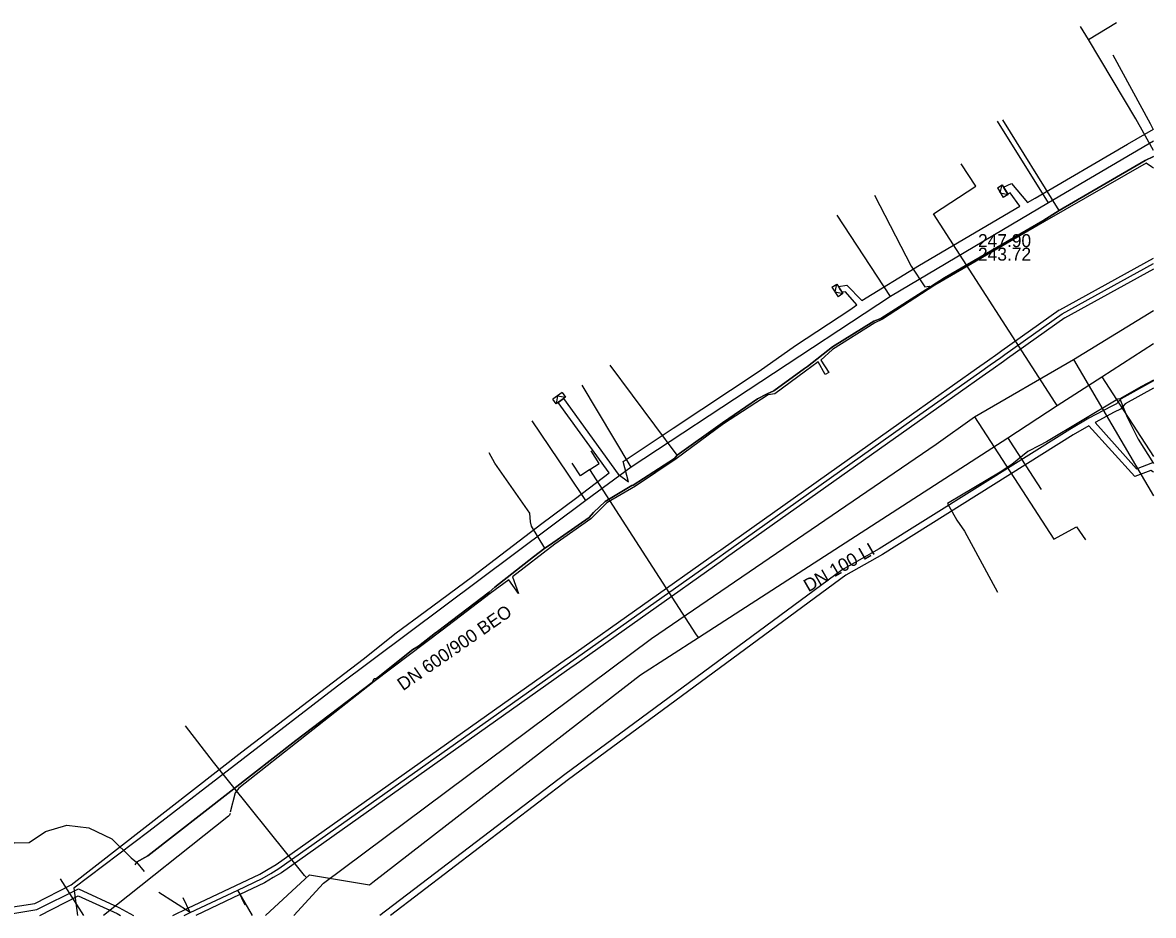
# Model space of a CAD drawing. Extents: x -600391 to -599491, y -1160176 to -1159402.
# Drawn here: x -599560.4 to -599490.8, y -1160176.1 to -1160121.1 of the extents above; entities that cross this region are included whole.
import ezdxf

# ---------------------------------------------------------------- set-up
doc = ezdxf.new("R2010")
doc.units = 0
for name, color, linetype in [('31', 7, 'Continuous'), ('UPC_ok_linie', 7, 'Continuous'), ('Vrstva 1', 7, 'Continuous'), ('Vrstva 10', 7, 'Continuous'), ('Vrstva 12', 7, 'Continuous'), ('Vrstva 13', 7, 'Continuous'), ('Vrstva 15', 7, 'Continuous'), ('Vrstva 16', 7, 'Continuous'), ('Vrstva 42', 7, 'Continuous'), ('Vrstva 43', 7, 'Continuous'), ('Vrstva 55', 7, 'Continuous'), ('Vrstva 9', 7, 'Continuous')]:
    doc.layers.add(name, color=color, linetype=linetype)

# ---------------------------------------------------------------- blocks, each defined once
blk = doc.blocks.new('NN630')
at = {"layer": '31'}
for points in [[(0, -0.7), (-0.7, 0)], [(-0.7, -0.7), (-0.7, 0), (0.7, 0), (0.7, -0.7)], [(-0.7, -0.7), (0.7, -0.7)], [(0, -0.7), (0.7, 0)]]:
    blk.add_lwpolyline(points, dxfattribs=at)

msp = doc.modelspace()

# ---------------------------------------------------------------- linework, layer by layer
at = {"layer": 'UPC_ok_linie'}
for p, q in [((-599496.57, -1160132.67), (-599500.056, -1160127.084)), ((-599520.12, -1160147.73), (-599524.244, -1160142.195)), ((-599553.42, -1160172.81), (-599552.943, -1160173.385))]:
    msp.add_line(p, q, dxfattribs=at)
for points in [[(-599490.773, -1160127.688), (-599490.96, -1160127.33), (-599493.246, -1160123.094)], [(-599490.773, -1160129.332), (-599491.27, -1160129.58), (-599496.57, -1160132.67), (-599497.59, -1160133.29), (-599503.65, -1160136.8), (-599504.44, -1160137.32), (-599504.508, -1160137.366), (-599504.56, -1160137.4), (-599507.57, -1160139.31)], [(-599496.57, -1160132.67), (-599491.27, -1160129.58), (-599490.773, -1160129.332)], [(-599507.946, -1160131.709), (-599505.69, -1160136.09), (-599504.86, -1160137.36), (-599504.58, -1160137.33), (-599504.508, -1160137.366)], [(-599504.508, -1160137.366), (-599504.44, -1160137.32), (-599503.65, -1160136.8), (-599497.59, -1160133.29), (-599496.57, -1160132.67)], [(-599520.12, -1160147.73), (-599517.32, -1160145.74), (-599515.16, -1160144.26), (-599514.56, -1160143.95), (-599514.16, -1160143.76), (-599512.26, -1160142.39), (-599512.08, -1160142.27), (-599510.54, -1160141.05), (-599507.99, -1160139.47), (-599507.57, -1160139.31), (-599504.56, -1160137.4), (-599504.508, -1160137.366)], [(-599507.57, -1160139.31), (-599507.99, -1160139.47), (-599510.54, -1160141.05), (-599512.08, -1160142.27), (-599512.26, -1160142.39), (-599514.16, -1160143.76), (-599514.56, -1160143.95), (-599515.16, -1160144.26), (-599517.32, -1160145.74), (-599520.12, -1160147.73), (-599520.27, -1160147.93), (-599522.82, -1160149.57), (-599522.91, -1160149.6), (-599524.55, -1160150.58), (-599525.27, -1160151.26), (-599525.53, -1160151.57), (-599527.97, -1160153.28), (-599528.26, -1160153.47), (-599528.96, -1160154), (-599531.35, -1160155.86), (-599531.7, -1160156.18), (-599534.87, -1160158.59), (-599535, -1160158.67), (-599536.05, -1160159.49), (-599536.4, -1160159.71), (-599538.64, -1160161.48), (-599538.77, -1160161.51), (-599538.9, -1160161.73), (-599543.61, -1160165.31), (-599547.6, -1160168.42), (-599552.72, -1160172.42), (-599553.42, -1160172.81), (-599553.52, -1160172.96)], [(-599490.773, -1160143.111), (-599491.54, -1160143.52), (-599492.85, -1160144.26)], [(-599492.85, -1160144.26), (-599492.97, -1160144.29), (-599497.35, -1160146.92), (-599497.79, -1160147.13), (-599498.51, -1160147.51), (-599499.5, -1160148.31), (-599500.21, -1160148.77), (-599503.46, -1160150.7), (-599502.89, -1160151.74), (-599502.4, -1160152.42), (-599500.374, -1160156.168)], [(-599492.85, -1160144.26), (-599492.38, -1160145.39), (-599491.72, -1160146.74), (-599490.773, -1160148.25)], [(-599528.26, -1160153.47), (-599529.09, -1160152.11), (-599529.14, -1160151.84), (-599529.19, -1160151.31), (-599531.35, -1160148.22), (-599531.698, -1160147.59)], [(-599528.26, -1160153.47), (-599527.97, -1160153.28), (-599525.53, -1160151.57), (-599525.27, -1160151.26), (-599524.55, -1160150.58), (-599522.91, -1160149.6), (-599522.82, -1160149.57), (-599520.27, -1160147.93), (-599520.12, -1160147.73)], [(-599553.42, -1160172.81), (-599552.72, -1160172.42), (-599547.6, -1160168.42), (-599543.61, -1160165.31), (-599538.9, -1160161.73), (-599538.77, -1160161.51), (-599538.64, -1160161.48), (-599536.4, -1160159.71), (-599536.05, -1160159.49), (-599535, -1160158.67), (-599534.87, -1160158.59), (-599531.7, -1160156.18), (-599531.35, -1160155.86), (-599528.96, -1160154), (-599528.26, -1160153.47)], [(-599561.99, -1160171.02), (-599560.93, -1160171.62), (-599560.04, -1160171.59), (-599559.02, -1160170.91), (-599557.72, -1160170.53), (-599556.35, -1160170.69), (-599554.93, -1160171.36), (-599553.75, -1160172.53), (-599553.42, -1160172.81)]]:
    msp.add_lwpolyline(points, dxfattribs=at)
at = {"layer": 'Vrstva 1'}
msp.add_line((-599546.282, -1160176.079), (-599547.18, -1160174.518), dxfattribs=at)
msp.add_lwpolyline([(-599550.117, -1160175.91), (-599552.05, -1160174.663)], dxfattribs=at)
at = {"layer": 'Vrstva 10'}
for p, q in [((-599496.542, -1160138.77), (-599490.773, -1160135.589)), ((-599490.773, -1160136.275), (-599496.252, -1160139.296))]:
    msp.add_line(p, q, dxfattribs=at)
for points in [[(-599545.305, -1160173.238), (-599544.81, -1160172.944), (-599526.921, -1160160.275), (-599526.826, -1160160.21), (-599517.663, -1160153.721), (-599517.427, -1160153.554), (-599505.674, -1160145.232), (-599501.664, -1160142.392), (-599500.998, -1160141.925), (-599500.352, -1160141.466), (-599500.099, -1160141.286), (-599496.57, -1160138.788)], [(-599496.224, -1160139.278), (-599499.752, -1160141.776), (-599500.005, -1160141.955), (-599500.652, -1160142.415), (-599501.319, -1160142.883), (-599505.328, -1160145.721), (-599517.08, -1160154.044), (-599517.317, -1160154.211), (-599526.482, -1160160.701), (-599526.577, -1160160.767), (-599544.482, -1160173.448), (-599544.999, -1160173.754)], [(-599551.174, -1160176.079), (-599550.246, -1160175.639), (-599547.308, -1160174.247), (-599545.812, -1160173.538), (-599545.305, -1160173.238)], [(-599544.999, -1160173.754), (-599545.53, -1160174.068), (-599547.052, -1160174.789), (-599549.773, -1160176.079)]]:
    msp.add_lwpolyline(points, dxfattribs=at)
at = {"layer": 'Vrstva 13'}
msp.add_line((-599494.777, -1160122.125), (-599493.049, -1160121.089), dxfattribs=at)
for points in [[(-599490.773, -1160128.967), (-599491.847, -1160127.012), (-599494.777, -1160122.125), (-599495.261, -1160121.319)], [(-599496.691, -1160144.682), (-599496.822, -1160144.48), (-599504.328, -1160132.863), (-599501.711, -1160131.172), (-599502.61, -1160129.78)], [(-599538.86, -1160174.03), (-599524.739, -1160163.098), (-599522.365, -1160161.271), (-599518.805, -1160158.971), (-599499.744, -1160146.654), (-599496.691, -1160144.682), (-599493.948, -1160142.909), (-599490.773, -1160140.857)], [(-599493.948, -1160142.909), (-599492.819, -1160144.656), (-599490.773, -1160147.822)], [(-599499.744, -1160146.654), (-599499.609, -1160146.864), (-599497.684, -1160149.842)], [(-599525.491, -1160148.623), (-599524.906, -1160148.251), (-599525.408, -1160147.464)], [(-599525.491, -1160148.623), (-599526.073, -1160148.999), (-599526.579, -1160148.215)], [(-599518.805, -1160158.971), (-599518.963, -1160158.727), (-599525.491, -1160148.623)], [(-599542.943, -1160173.748), (-599543.065, -1160173.616), (-599548.679, -1160166.635), (-599550.391, -1160164.399)], [(-599545.471, -1160176.079), (-599542.76, -1160173.58), (-599539.07, -1160174.2), (-599538.86, -1160174.03)]]:
    msp.add_lwpolyline(points, dxfattribs=at)
at = {"layer": 'Vrstva 16'}
msp.add_line((-599495.7, -1160141.84), (-599490.773, -1160150.233), dxfattribs=at)
for points in [[(-599497.24, -1160132.18), (-599500.37, -1160127.15)], [(-599490.773, -1160128.397), (-599497.24, -1160132.18), (-599506.97, -1160137.96), (-599522.95, -1160148.47), (-599525.73, -1160150.52), (-599541.04, -1160161.95), (-599552.66, -1160170.92), (-599557.27, -1160174.4), (-599557.046, -1160176.079)], [(-599506.97, -1160137.96), (-599510.26, -1160132.94)], [(-599543.725, -1160176.079), (-599541.89, -1160174.09), (-599521.69, -1160159.02), (-599504.16, -1160147.05), (-599501.79, -1160145.37), (-599495.7, -1160141.84), (-599490.773, -1160138.826)], [(-599522.95, -1160148.47), (-599524.02, -1160146.68), (-599525.97, -1160143.42)], [(-599501.79, -1160145.37), (-599496.91, -1160152.9), (-599495.51, -1160152.14), (-599494.96, -1160152.95)], [(-599525.73, -1160150.52), (-599526.86, -1160148.85), (-599529.05, -1160145.62)]]:
    msp.add_lwpolyline(points, dxfattribs=at)
at = {"layer": 'Vrstva 42'}
for points in [[(-599634.504, -1160126.471), (-599634.85, -1160127.03), (-599636.409, -1160130.583), (-599637.001, -1160132.119), (-599631.19, -1160136.042), (-599627.361, -1160137.785), (-599613.568, -1160146.889), (-599607.969, -1160150.583), (-599600.821, -1160154.928), (-599599.757, -1160155.61), (-599599.533, -1160157.106), (-599598.166, -1160157.99), (-599591.349, -1160161.586), (-599589.694, -1160162.277), (-599587.309, -1160162.246), (-599577.898, -1160167.226), (-599572.749, -1160170.004), (-599561.645, -1160176.061), (-599559.549, -1160175.724), (-599556.984, -1160174.448), (-599554.507, -1160175.592), (-599553.596, -1160176.079)], [(-599523.116, -1160149.38), (-599523.439, -1160148.112), (-599520.352, -1160146.07), (-599515.058, -1160142.557), (-599512.823, -1160140.977), (-599509.473, -1160138.77), (-599509.048, -1160138.464), (-599509.748, -1160137.661), (-599509.952, -1160137.697), (-599510.092, -1160137.49), (-599510.17, -1160137.348), (-599509.665, -1160137.26), (-599508.74, -1160138.208), (-599505.181, -1160136.038), (-599498.991, -1160132.396), (-599499.587, -1160131.579), (-599499.747, -1160131.646), (-599499.905, -1160131.385), (-599500.004, -1160131.231), (-599499.505, -1160130.993), (-599498.53, -1160132.167), (-599498.056, -1160131.898), (-599492.361, -1160128.579), (-599490.773, -1160127.643)], [(-599490.773, -1160143.146), (-599492.759, -1160144.264), (-599493.038, -1160144.573), (-599493.375, -1160144.73), (-599494.753, -1160145.457), (-599495.924, -1160146.146), (-599507.66, -1160153.502), (-599509.938, -1160154.788), (-599527.035, -1160167.399), (-599538.423, -1160176.079)], [(-599490.773, -1160143.605), (-599492.506, -1160144.58), (-599492.795, -1160144.901), (-599493.197, -1160145.088), (-599494.361, -1160145.714), (-599491.808, -1160148.58), (-599490.817, -1160148.193), (-599490.773, -1160148.225)], [(-599561.573, -1160175.644), (-599559.675, -1160175.339), (-599557.438, -1160174.188), (-599546.922, -1160166.008), (-599539.445, -1160160.307), (-599537.427, -1160158.68), (-599535.645, -1160157.357), (-599532.725, -1160155.199), (-599528.456, -1160151.939), (-599526.368, -1160150.41), (-599524.296, -1160148.83), (-599527.441, -1160144.48), (-599527.279, -1160144.363), (-599527.117, -1160144.245), (-599523.742, -1160148.912), (-599523.116, -1160149.38)], [(-599490.773, -1160148.773), (-599490.937, -1160148.669), (-599491.92, -1160149.054), (-599494.755, -1160145.918), (-599495.716, -1160146.488), (-599507.455, -1160153.846), (-599509.72, -1160155.124), (-599526.795, -1160167.719), (-599537.763, -1160176.079)], [(-599559.363, -1160176.079), (-599557.006, -1160174.865), (-599554.608, -1160175.97), (-599554.404, -1160176.079)]]:
    msp.add_lwpolyline(points, dxfattribs=at)
at = {"layer": 'Vrstva 55'}
for points in [[(-599490.773, -1160130.057), (-599490.88, -1160129.98), (-599491.21, -1160129.74), (-599497.49, -1160133.33), (-599504.23, -1160137.27), (-599507.46, -1160139.36), (-599507.94, -1160139.58), (-599510.54, -1160141.23), (-599511.257, -1160141.87), (-599510.758, -1160142.631), (-599510.997, -1160142.766), (-599511.424, -1160141.985), (-599512.2, -1160142.55), (-599514.09, -1160143.96), (-599514.51, -1160144.02), (-599517.26, -1160145.81), (-599520.17, -1160147.96), (-599522.68, -1160149.65), (-599524.44, -1160150.66), (-599525.43, -1160151.65), (-599527.64, -1160153.21), (-599530.256, -1160155.219), (-599529.888, -1160156.256), (-599530.472, -1160155.414), (-599531.64, -1160156.26), (-599534.58, -1160158.51), (-599538.77, -1160161.67), (-599547.12, -1160168.24), (-599547.34, -1160168.53), (-599547.65, -1160169.72)], [(-599547.65, -1160169.81), (-599547.68, -1160169.91), (-599547.743, -1160169.959), (-599555.441, -1160176.079)]]:
    msp.add_lwpolyline(points, dxfattribs=at)
at = {"layer": 'Vrstva 9'}
for p, q in [((-599496.397, -1160139.033), (-599490.773, -1160135.932)), ((-599556.671, -1160176.079), (-599558.095, -1160173.828)), ((-599547.18, -1160174.518), (-599546.752, -1160175.422)), ((-599550.117, -1160175.91), (-599550.545, -1160175.006))]:
    msp.add_line(p, q, dxfattribs=at)
for points in [[(-599545.152, -1160173.496), (-599544.646, -1160173.196), (-599526.749, -1160160.521), (-599526.654, -1160160.456), (-599517.49, -1160153.966), (-599517.253, -1160153.799), (-599505.501, -1160145.477), (-599501.492, -1160142.638), (-599500.825, -1160142.17), (-599500.178, -1160141.71), (-599499.925, -1160141.531), (-599496.397, -1160139.033)], [(-599550.474, -1160176.079), (-599550.117, -1160175.91), (-599547.18, -1160174.518), (-599545.671, -1160173.803), (-599545.152, -1160173.496)]]:
    msp.add_lwpolyline(points, dxfattribs=at)

# ---------------------------------------------------------------- block references
at = {"layer": 'Vrstva 43', "xscale": 0.5, "yscale": 0.5}
for p, rotation in [((-599499.905, -1160131.385), -59.00000000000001), ((-599510.092, -1160137.49), -57.00000000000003), ((-599527.279, -1160144.363), -144.00000000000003)]:
    msp.add_blockref('NN630', p, dxfattribs=dict(at, rotation=rotation))

# ---------------------------------------------------------------- texts
at = {"layer": 'Vrstva 12'}
for s, p in [('247.90', (-599501.578, -1160134.918)), ('243.72', (-599501.578, -1160135.75))]:
    msp.add_text(s, height=0.8, dxfattribs=at).set_placement(p)
msp.add_text('DN 600/900 BEO', height=0.8, rotation=34.77982, dxfattribs=at).set_placement((-599537, -1160162.274))
at = {"layer": 'Vrstva 15'}
msp.add_text('DN 100 LI', height=0.8, rotation=30.01764, dxfattribs=at).set_placement((-599512.025, -1160156.187))

doc.saveas('drawing.dxf')
